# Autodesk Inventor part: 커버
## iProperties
Company: 한국ATC센터
Created: 2014-07
Part Number: 커버
Document SubType Name: 모델링
Designer: KYOUNG IL JANG
변환 표준: STEP AP214IS
파일 이름: C:\Users\SeoGD\Desktop\?쒗뿕\而ㅻ쾭-1.stp
전처리기: Build: 253, Release: 2010 SP1 - Date: Wed 07/29/2009
전송 단위: 밀리미터
불확실성: 0.01
Author: KYOUNG IL JANG
